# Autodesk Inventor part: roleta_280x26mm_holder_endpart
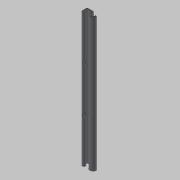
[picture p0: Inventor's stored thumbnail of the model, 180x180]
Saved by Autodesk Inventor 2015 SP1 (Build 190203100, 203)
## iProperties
Created: 2015-06
Part Number: roleta_280x26mm_holder_endpart
Material: Generic
Document SubType Name: Modeling
Designer: uidn2323
Density: 1 g/cm^3
Appearance: Default
Author: uidn2323
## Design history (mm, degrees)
sketch "Sketch9"
  geometry: L1 (13.17, -3.952)-(13.17, -2.165); L2 (11.706, -0.701)-(7.314, -0.701); L3 (15.979, -0.698)-(15.979, -4.198); L4 (0.24, -6.581)-(0.24, -0.701); L5 (13.17, 2.227)-(3.168, 2.227); L6 (7.314, -0.701)-(3.24, -0.701); L7 (3.24, -0.701)-(3.24, -1.596); L8 (5.24, -6.581)-(5.24, -4.453); L9 (26.346, -4.113)-(23.067, -2.32); L10 (8.827, -1.117)-(12.721, -1.117); L11 (26.346, -4.113)-(26.346, -7.113); L12 (19.933, -4.8)-(19.933, -4.453); L13 (19.933, -11.621)-(-0.777, -11.621); L14 (0.24, -4.113)-(0.24, -8.298); L15 (3.24, -1.596)-(3.24, -4.926); A1 r 2.928 centre (13.051, -0.698) between (15.979, -0.698) and (13.17, 2.227); A2 r 1.464 centre (11.706, -2.165) between (13.17, -2.165) and (11.706, -0.701); A3 r 2.928 centre (3.168, -0.701) between (3.168, 2.227) and (0.24, -0.701); A4 r 4 centre (19.933, -4.805) between (15.979, -4.198) and (23.067, -2.32); A5 r 6.816 centre (19.933, -4.805) between (13.17, -3.952) and (26.346, -7.113); A6 r 3.395 centre (3.635, -8.298) between (0.24, -8.298) and (3.24, -4.926); 4 further points
  constraints: 30 end point, 13 point on circle, 6 centre point, 6 tangent, 5 horizontal, 4 vertical, 2 point on line, 1 coincident, 1 perpendicular
  dimensions: "d179" = 6.816 radius of A5; "d180" = 4 radius of A4; "d181" = 2.928 radius of A1; "d182" = 10.00212 distance of L5.start L5.end; "d183" = 2.928 radius of A3; "d184" = 1.464 radius of A2; "d185" = 4.392 distance of L2.start L2.end; "d186" = 2.92801 distance between parallel lines of L5 L2; "d211" = 3 distance between parallel lines of L14 L15
extrude "Extrusion3" join sketch "Sketch9" distance "d189" = 287; taper "d190" = 0 deg
sketch "Sketch10"
  geometry: L1 (13.17, -3.952)-(13.17, -2.165); L2 (11.706, -0.701)-(7.314, -0.701); L3 (2.499, -4.802)-(19.933, -4.802); L4 (15.979, -0.698)-(15.979, -4.198); L5 (0.24, -4.8)-(0.24, -0.701); L6 (13.17, 2.227)-(3.168, 2.227); L7 (7.314, -0.701)-(5.516, -0.701); L8 (5.516, -0.701)-(3.476, -0.701); L9 (3.476, -0.701)-(3.476, -1.809); L10 (3.24, -4.8)-(3.24, -4.453); L11 (23.029, -2.299)-(23.039, -2.285); L12 (2.134, -4.8)-(19.568, -4.8); L13 (26.346, -4.113)-(23.029, -2.299); L14 (26.346, -4.113)-(26.346, -7.113); L15 (19.933, -4.8)-(19.933, -4.453); A1 r 2.928 centre (13.051, -0.698) between (15.979, -0.698) and (13.17, 2.227); A2 r 1.464 centre (11.706, -2.165) between (13.17, -2.165) and (11.706, -0.701); A3 r 2.928 centre (3.168, -0.701) between (3.168, 2.227) and (0.24, -0.701); A4 r 4 centre (19.933, -4.805) between (15.979, -4.198) and (23.039, -2.285); A5 r 6.816 centre (19.933, -4.805) between (13.17, -3.952) and (26.346, -7.113); A6 r 3 centre (3.24, -4.8) between (0.24, -4.8) and (3.476, -1.809); 1 further point
  constraints: 31 end point, 12 point on circle, 6 centre point, 6 horizontal, 4 tangent, 4 vertical, 2 coincident, 1 perpendicular
  dimensions: "d202" = 6.816 radius of A5; "d203" = 4 radius of A4; "d204" = 2.928 radius of A1; "d205" = 10.00212 distance of L6.start L6.end; "d206" = 2.928 radius of A3; "d207" = 1.464 radius of A2; "d208" = 4.392 distance of L2.start L2.end; "d209" = 2.92801 distance between parallel lines of L6 L2; "d210" = 3 radius of A6
sketch "Sketch11"
  geometry: L1 (13.17, -3.952)-(13.17, -2.165); L2 (11.706, -0.701)-(7.314, -0.701); L3 (15.979, -0.698)-(15.979, -4.198); L4 (13.17, 2.227)-(3.168, 2.227); L5 (7.314, -0.701)-(3.24, -0.701); L6 (3.24, -0.701)-(3.24, -1.596); L7 (26.346, -4.113)-(23.067, -2.32); L8 (26.346, -4.113)-(26.346, -7.113); L9 (19.933, -4.8)-(19.933, -4.453); L10 (3.24, -1.596)-(3.24, -4.926); L11 (0.24, -8.298)-(0.24, -0.701); L12 (2.44, -5.995)-(2.44, -1.596); L13 (2.44, -1.596)-(2.44, 0.099); L14 (2.44, 0.099)-(7.314, 0.099); L15 (7.314, 0.099)-(11.706, 0.099); L16 (13.97, -2.165)-(13.97, -4.004); L17 (25.546, -6.969)-(25.546, -4.588); L18 (25.546, -4.588)-(24.683, -4.116); L19 (15.179, -4.139)-(15.179, -0.698); L20 (13.153, 1.427)-(3.168, 1.427); L21 (1.04, -8.298)-(1.04, -0.701); A1 r 2.928 centre (13.051, -0.698) between (15.979, -0.698) and (13.17, 2.227); A2 r 1.464 centre (11.706, -2.165) between (13.17, -2.165) and (11.706, -0.701); A3 r 2.928 centre (3.168, -0.701) between (3.168, 2.227) and (0.24, -0.701); A4 r 4 centre (19.933, -4.805) between (15.979, -4.198) and (23.067, -2.32); A5 r 6.816 centre (19.933, -4.805) between (13.17, -3.952) and (26.346, -7.113); A6 r 3.395 centre (3.635, -8.298) between (0.24, -8.298) and (3.24, -4.926); A7 r 2.928 centre (3.168, -0.701) between (3.168, 2.227) and (0.24, -0.701) reference; A8 r 2.595 centre (3.635, -8.298) between (1.04, -8.298) and (2.44, -5.995); A9 r 2.264 centre (11.706, -2.165) between (13.97, -2.165) and (11.706, 0.099); A10 r 6.016 centre (19.933, -4.805) between (13.97, -4.004) and (25.546, -6.969); A11 r 4.8 centre (19.933, -4.805) between (15.179, -4.139) and (24.683, -4.116); A12 r 2.128 centre (13.051, -0.698) between (15.179, -0.698) and (13.153, 1.427); A13 r 2.128 centre (3.168, -0.701) between (3.168, 1.427) and (1.04, -0.701); 2 further points
  constraints: 42 end point, 25 point on circle, 12 centre point, 4 tangent, 4 vertical, 3 horizontal, 1 coincident, 14 other
  dimensions: "d225" = 0.8 distance between parallel lines of L4 L20
extrude "Extrusion4" cut sketch "Sketch11" stored distance "d223" = 10; taper "d224" = 0 deg
sketch "Sketch12"
  geometry: L1 (-9.737, -143.5)-(30.965, -143.5); L2 (5.002, -143.5)-(5.002, -191.5); L3 (5.002, -143.5)-(5.002, -95.5); L4 (10.002, 0)-(10.002, -287) reference; L5 (9.985, -287)-(0, -287) reference; C1 r 2.5 at (5.002, -191.5); C2 r 2.5 at (5.002, -95.5); 1 further point
  constraints: 6 end point, 2 centre point, 2 coincident, 1 horizontal, 1 point on line, 1 symmetric about line, 1 vertical
  dimensions: "d228" = 48 distance of L2.start L2.end; "d229" = 5 distance between parallel lines of L4 L2; "d230" = 5 diameter of C1; "d231" = 5 diameter of C2; "d239" = 143.5 distance between parallel lines of L1 L5
extrude "Extrusion6" cut sketch "Sketch12" distance "d232" = 5; taper "d233" = 0 deg
sketch "Sketch13"
  geometry: L1 (13.17, -3.952)-(13.17, -2.165); L2 (11.706, -0.701)-(7.314, -0.701); L3 (15.979, -0.698)-(15.979, -4.198); L4 (13.17, 2.227)-(3.168, 2.227); L5 (7.314, -0.701)-(3.24, -0.701); L6 (3.24, -0.701)-(3.24, -1.596); L7 (26.346, -4.113)-(23.067, -2.32); L8 (26.346, -4.113)-(26.346, -7.113); L9 (19.933, -4.8)-(19.933, -4.453); L10 (3.24, -1.596)-(3.24, -4.926); L11 (0.24, -8.298)-(0.24, -0.701); L12 (2.44, -5.995)-(2.44, -1.596); L13 (2.44, -1.596)-(2.44, 0.099); L14 (2.44, 0.099)-(7.314, 0.099); L15 (7.314, 0.099)-(11.706, 0.099); L16 (13.97, -2.165)-(13.97, -4.004); L17 (25.546, -6.969)-(25.546, -4.588); L18 (25.546, -4.588)-(24.683, -4.116); L19 (15.179, -4.139)-(15.179, -0.698); L20 (13.153, 1.427)-(3.168, 1.427); L21 (1.04, -8.298)-(1.04, -0.701); A1 r 2.928 centre (13.051, -0.698) between (15.979, -0.698) and (13.17, 2.227); A2 r 1.464 centre (11.706, -2.165) between (13.17, -2.165) and (11.706, -0.701); A3 r 2.928 centre (3.168, -0.701) between (3.168, 2.227) and (0.24, -0.701); A4 r 4 centre (19.933, -4.805) between (15.979, -4.198) and (23.067, -2.32); A5 r 6.816 centre (19.933, -4.805) between (13.17, -3.952) and (26.346, -7.113); A6 r 3.395 centre (3.635, -8.298) between (0.24, -8.298) and (3.24, -4.926); A7 r 2.928 centre (3.168, -0.701) between (3.168, 2.227) and (0.24, -0.701); A8 r 2.595 centre (3.635, -8.298) between (1.04, -8.298) and (2.44, -5.995); A9 r 2.264 centre (11.706, -2.165) between (13.97, -2.165) and (11.706, 0.099); A10 r 6.016 centre (19.933, -4.805) between (13.97, -4.004) and (25.546, -6.969); A11 r 4.8 centre (19.933, -4.805) between (15.179, -4.139) and (24.683, -4.116); A12 r 2.128 centre (13.051, -0.698) between (15.179, -0.698) and (13.153, 1.427); A13 r 2.128 centre (3.168, -0.701) between (3.168, 1.427) and (1.04, -0.701); 3 further points
  constraints: 42 end point, 27 point on circle, 13 centre point, 4 tangent, 4 vertical, 3 horizontal, 1 coincident, 14 other
  dimensions: "d234" = 0.8 distance between parallel lines of L4 L20
extrude "Extrusion7" join sketch "Sketch13" distance "d235" = 287; taper "d236" = 0 deg
extrude "Extrusion8" cut sketch "Sketch11" distance "d237" = 287; taper "d238" = 0 deg
extrude "Extrusion9" cut sketch "Sketch12" distance "d240" = 287; taper "d241" = 0 deg
sketch "Sketch14"
  geometry: C1 r 4.75 at (4.922, -95.465); C2 r 4.75 at (4.922, -191.446); 1 further point
  constraints: 2 centre point
extrude "Extrusion10" cut sketch "Sketch14" distance "d242" = 287; taper "d243" = 0 deg
body "Solid1"
other parameters: "d122" = 6.83405, "d123" = 4.99923
